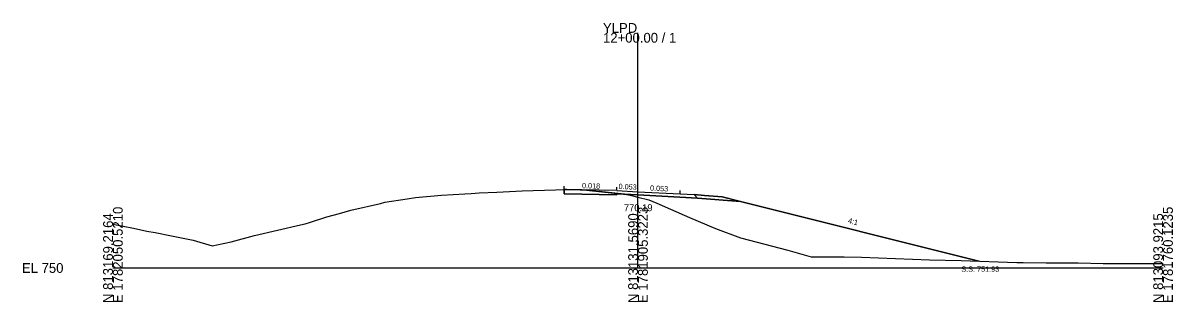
# Model space of a CAD drawing. Extents: x -26 to 353, y -10 to 9080.
# Drawn here: x -25.7 to 302.8, y 1990.3 to 2069.9 of the extents above; entities that cross this region are included whole.
import ezdxf

# ---------------------------------------------------------------- set-up
doc = ezdxf.new("R2010")
doc.units = 0
for name, color, linetype in [('Exist Cross Section Cell', 7, 'Continuous'), ('Exist XS Center Line Elevation Label', 7, 'Continuous'), ('Exist XS Ground Line', 7, 'Continuous'), ('Prop XS Dump Level', 7, 'Continuous'), ('Prop XS Earthwork Shape', 7, 'Continuous'), ('Prop XS EOT Tick Mark', 7, 'Continuous'), ('Prop XS Finish Grade', 7, 'Continuous'), ('Prop XS Finish Grade Earthwork', 7, 'Continuous'), ('Prop XS Finish Grade Paved Shoulder', 7, 'Continuous'), ('Prop XS Finish Grade Pavement', 7, 'Continuous'), ('Prop XS Pvmt Edge Slope', 7, 'Continuous'), ('Prop XS SE Text', 7, 'Continuous'), ('Prop XS Side Slope Text', 7, 'Continuous'), ('Prop XS SS Elevation Text', 7, 'Continuous'), ('Prop XS Subgrade Earthwork', 7, 'Continuous'), ('Scratch_Level_3', 7, 'Continuous')]:
    doc.layers.add(name, color=color, linetype=linetype)

msp = doc.modelspace()

# ---------------------------------------------------------------- linework, layer by layer
at = {"layer": 'Exist Cross Section Cell'}
for p, q in [((150, 2000), (150, 2067.08)), ((0, 2000), (150, 2000)), ((150, 2000), (300, 2000))]:
    msp.add_line(p, q, dxfattribs=at)
at = {"layer": 'Exist XS Ground Line'}
for p, q in [((86.44, 2020.14), (93.82, 2020.77)), ((93.82, 2020.77), (100.57, 2021.15)), ((100.57, 2021.15), (102.31, 2021.27)), ((102.31, 2021.27), (104.63, 2021.41)), ((104.63, 2021.41), (109.68, 2021.67)), ((109.68, 2021.67), (116.87, 2022)), ((116.87, 2022), (126.44, 2022.28)), ((126.44, 2022.28), (128.92, 2022.36)), ((128.92, 2022.36), (129.71, 2022.36)), ((129.71, 2022.36), (133.51, 2022.32)), ((133.51, 2022.32), (135.32, 2022.16)), ((135.32, 2022.16), (146.74, 2021)), ((146.74, 2021), (147.8, 2020.73)), ((147.8, 2020.73), (150, 2020.19)), ((68.01, 2016.46), (76.4, 2018.44)), ((76.4, 2018.44), (77.67, 2018.76)), ((77.67, 2018.76), (84.04, 2019.76)), ((84.04, 2019.76), (86.44, 2020.14)), ((150, 2020.19), (153.06, 2019.45)), ((153.06, 2019.45), (155.35, 2018.53)), ((155.35, 2018.53), (164.7, 2014.4)), ((56.19, 2012.93), (61.12, 2014.58)), ((61.12, 2014.58), (64.76, 2015.58)), ((64.76, 2015.58), (68.01, 2016.46)), ((164.7, 2014.4), (172.15, 2011.3)), ((0, 2012.46), (5.91, 2011.35)), ((5.91, 2011.35), (9.69, 2010.51)), ((40.44, 2009.27), (53.62, 2012.27)), ((53.62, 2012.27), (54.88, 2012.58)), ((54.88, 2012.58), (56.19, 2012.93)), ((172.15, 2011.3), (179.25, 2008.56)), ((9.69, 2010.51), (12.1, 2010.09)), ((12.1, 2010.09), (16.72, 2009.17)), ((16.72, 2009.17), (22.9, 2007.91)), ((22.9, 2007.91), (28.36, 2006.34)), ((28.36, 2006.34), (33.74, 2007.45)), ((33.74, 2007.45), (40.44, 2009.27)), ((179.25, 2008.56), (192.77, 2005.06)), ((192.77, 2005.06), (199.49, 2003.19)), ((199.49, 2003.19), (208.89, 2003.14)), ((208.89, 2003.14), (213.83, 2003.09)), ((213.83, 2003.09), (233.3, 2002.33)), ((233.3, 2002.33), (242.32, 2002.09)), ((242.32, 2002.09), (258.27, 2001.6)), ((258.27, 2001.6), (260.05, 2001.57)), ((260.05, 2001.57), (266.59, 2001.49)), ((266.59, 2001.49), (269.85, 2001.46)), ((269.85, 2001.46), (270.2, 2001.45)), ((270.2, 2001.45), (270.71, 2001.46)), ((270.71, 2001.46), (275.72, 2001.46)), ((275.72, 2001.46), (282.9, 2001.3)), ((282.9, 2001.3), (288.11, 2001.28)), ((288.11, 2001.28), (295.03, 2001.31)), ((295.03, 2001.31), (300, 2001.27))]:
    msp.add_line(p, q, dxfattribs=at)
at = {"layer": 'Prop XS Dump Level'}
for p, q in [((144, 2022.09), (150, 2021.77)), ((150, 2021.77), (162, 2021.13))]:
    msp.add_line(p, q, dxfattribs=at)
at = {"layer": 'Prop XS Earthwork Shape'}
for points in [[(144, 2021.18), (146.15, 2021.06), (135.32, 2022.16), (133.51, 2022.32), (129.71, 2022.36), (128.92, 2022.36), (128.92, 2021.11), (144, 2020.84)], [(146.15, 2021.06), (146.74, 2021), (147.8, 2020.73), (150, 2020.19), (153.06, 2019.45), (155.35, 2018.53), (164.7, 2014.4), (172.15, 2011.3), (179.25, 2008.56), (192.77, 2005.06), (199.49, 2003.19), (208.89, 2003.14), (213.83, 2003.09), (233.3, 2002.33), (242.32, 2002.09), (247.39, 2001.93), (179.25, 2018.97), (166.97, 2019.95), (161.95, 2020.22), (149.95, 2020.86)]]:
    msp.add_lwpolyline(points, close=True, dxfattribs=at)
at = {"layer": 'Prop XS EOT Tick Mark'}
for p, q in [((128.92, 2022.36), (128.92, 2023.36)), ((144, 2022.09), (144, 2023.09)), ((162, 2021.13), (162, 2022.13))]:
    msp.add_line(p, q, dxfattribs=at)
at = {"layer": 'Prop XS Finish Grade'}
for p, q in [((166, 2020.92), (169, 2020.68)), ((169, 2020.68), (174, 2020.28)), ((174, 2020.28), (179.25, 2018.97))]:
    msp.add_line(p, q, dxfattribs=at)
at = {"layer": 'Prop XS Finish Grade Earthwork'}
msp.add_line((179.25, 2018.97), (247.39, 2001.93), dxfattribs=at)
at = {"layer": 'Prop XS Finish Grade Paved Shoulder'}
for p, q in [((144, 2022.09), (128.92, 2022.36)), ((162, 2021.13), (166, 2020.92))]:
    msp.add_line(p, q, dxfattribs=at)
at = {"layer": 'Prop XS Finish Grade Pavement'}
for p, q in [((144, 2022.09), (150, 2021.77)), ((150, 2021.77), (162, 2021.13))]:
    msp.add_line(p, q, dxfattribs=at)
at = {"layer": 'Prop XS Pvmt Edge Slope'}
msp.add_line((166, 2020.92), (166.97, 2019.95), dxfattribs=at)
at = {"layer": 'Prop XS Subgrade Earthwork'}
for p, q in [((128.92, 2021.11), (128.92, 2022.36)), ((144, 2020.84), (128.92, 2021.11)), ((144, 2021.18), (149.95, 2020.86)), ((144, 2020.84), (144, 2021.18)), ((149.95, 2020.86), (161.95, 2020.22)), ((161.95, 2020.22), (166.97, 2019.95)), ((166.97, 2019.95), (179.25, 2018.97))]:
    msp.add_line(p, q, dxfattribs=at)
at = {"layer": 'Scratch_Level_3'}
for p, q in [((169, 2020.68), (166, 2020.92)), ((166, 2020.92), (166.97, 2019.95)), ((174, 2020.28), (169, 2020.68)), ((166.97, 2019.95), (179.25, 2018.97)), ((179.25, 2018.97), (174, 2020.28))]:
    msp.add_line(p, q, dxfattribs=at)

# ---------------------------------------------------------------- texts
at = {"layer": 'Exist Cross Section Cell'}
for s, p in [('YLPD', (140, 2067.08)), ('12+00.00 / 1', (140, 2064.28)), ('EL 750', (-26, 1998.6))]:
    msp.add_text(s, height=2.8, dxfattribs=at).set_placement(p)
for s, p in [('E 1782050.5210', (2.8, 1990)), ('E 1781905.3223', (152.8, 1990)), ('E 1781760.1235', (302.8, 1990)), ('N 813169.2164', (0, 1990)), ('N 813131.5690', (150, 1990)), ('N 813093.9215', (300, 1990))]:
    msp.add_text(s, height=2.8, rotation=90, dxfattribs=at).set_placement(p)
at = {"layer": 'Exist XS Center Line Elevation Label'}
msp.add_text('770.19', height=2, dxfattribs=at).set_placement((145.97, 2016.19))
at = {"layer": 'Prop XS Dump Level'}
msp.add_text('Case4', height=0.04, dxfattribs=at).set_placement((174, 2020.24))
at = {"layer": 'Prop XS SE Text'}
for s, rotation, p in [('0.018', 358.4735, (133.99, 2022.77)), ('0.053', 356.9464, (144.41, 2022.57)), ('0.053', 356.9456, (153.41, 2022.09))]:
    msp.add_text(s, height=1.5, rotation=rotation, dxfattribs=at).set_placement(p)
at = {"layer": 'Prop XS Side Slope Text'}
msp.add_text('4:1', height=1.5, rotation=345.9638, dxfattribs=at).set_placement((209.88, 2012.86))
at = {"layer": 'Prop XS SS Elevation Text'}
msp.add_text('S.S. 751.93', height=1.5, dxfattribs=at).set_placement((242.37, 1998.93))

doc.saveas('drawing.dxf')
